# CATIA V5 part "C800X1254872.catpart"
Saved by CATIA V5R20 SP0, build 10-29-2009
Part number: C800X1254872
Source: Unknown
Property "A": "50"
Property "ARTICLENO": "C800X1254872"
Property "B": "23"
Property "BOMINFO": "C800X1254872"
Property "C": "91"
Property "CA": "C800X1254872"
Property "D1": "90"
Property "DES": "ROTATING EYEBOLT WITH RING Ton 12,5 M48x72"
Property "E": "86"
Property "H": "200"
Property "L": "72"
Property "LINA": "C800X1254872"
Property "NB": "C800X1254872"
Property "NBSYN": "$CODE."
Property "NN": "C800X"
Property "NT": "Rotating eyebolt with ring"
Property "SIZE": "M48"
Property "SUPPLIER": "CF"
Property "SW": "80"
Property "WEIGHT": "5200"
Property "WLL": "12.50"
Bounding box of the stored display mesh (mm): x -47.825 to 48, y -72 to 222.825, z -45 to 45
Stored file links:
  C:\Users\Utente\Desktop\3D files 800X\C800X1254872.catpart
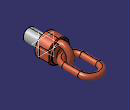
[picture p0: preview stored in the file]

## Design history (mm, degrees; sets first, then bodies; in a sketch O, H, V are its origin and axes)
Body1 "Geometry.1" (main body)
  Solid1 "C800X1254872.catpart": solid without history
